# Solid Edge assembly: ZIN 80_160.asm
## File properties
Title: Zylinder
Author: bmolnar
Template: iso metric assembly.asm
Last saved by: bmolnar
Revision: 25
Application: Solid Edge
Username: bmolnar
Dokumentum tartalom típus: 1
Document Number: ZIN 80/160
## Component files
Kit_1.par
Kit_2.par
Kolbenstange.par
Profilrohr.par
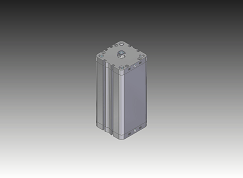
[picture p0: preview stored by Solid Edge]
